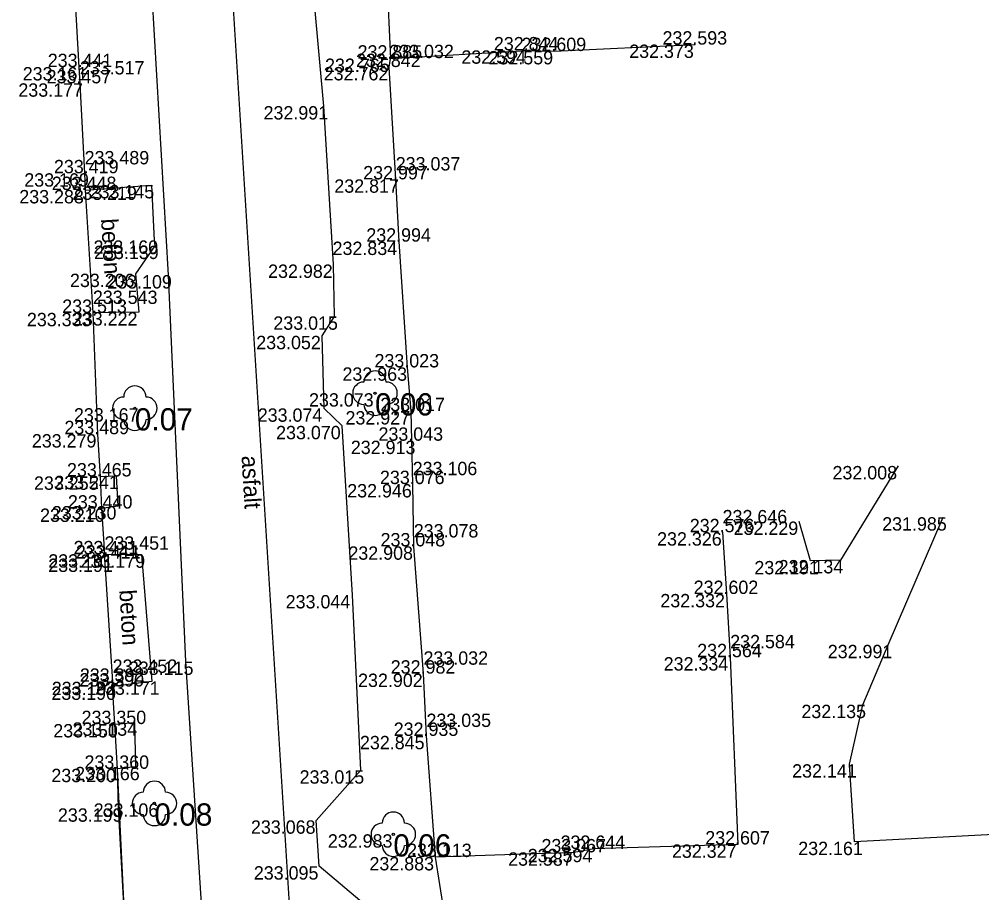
# Model space of a CAD drawing. Extents: x -599516 to -599132, y -1163668 to -1163119.
# Drawn here: x -599498.94 to -599477.33, y -1163341.49 to -1163321.87 of the extents above; entities that cross this region are included whole.
import ezdxf

# ---------------------------------------------------------------- set-up
doc = ezdxf.new("R2010")
doc.units = 0
for name, color, linetype in [('Bod-oznac1', 7, 'Continuous'), ('Bod-oznac2', 7, 'Continuous'), ('Bod-oznac3', 7, 'Continuous'), ('Bod-vyska1', 7, 'Continuous'), ('Bod-vyska2', 7, 'Continuous'), ('Bod-vyska3', 7, 'Continuous'), ('Z_cela-hrobu-dolni-linie', 7, 'Continuous'), ('Z_cela-hrobu-horni-linie', 7, 'Continuous'), ('Z_chodnik', 7, 'Continuous'), ('Z_kanalizace-destova', 7, 'Continuous'), ('Z_komunikace', 7, 'Continuous'), ('Z_nove-stromy-prumer-kmene', 7, 'Continuous'), ('Z_popis-budov-povrchu', 7, 'Continuous'), ('Z_stromy-nove-vysazene', 7, 'Continuous'), ('Z_zpevnene-plochy', 7, 'Continuous')]:
    doc.layers.add(name, color=color, linetype=linetype)

msp = doc.modelspace()

# ---------------------------------------------------------------- linework, layer by layer
at = {"layer": 'Bod-oznac1'}
for p, q in [((-599487.531, -1163322.57), (-599487.531, -1163322.57)), ((-599486.933, -1163322.585), (-599486.933, -1163322.585)), ((-599483.761, -1163322.44), (-599483.761, -1163322.44)), ((-599490.602, -1163322.755), (-599490.602, -1163322.755)), ((-599497.6, -1163322.946), (-599497.6, -1163322.946)), ((-599490.632, -1163322.944), (-599490.632, -1163322.944)), ((-599497.579, -1163323.311), (-599497.579, -1163323.311)), ((-599492.1, -1163323.823), (-599492.1, -1163323.823)), ((-599497.472, -1163325.331), (-599497.472, -1163325.331)), ((-599496.383, -1163325.629), (-599496.383, -1163325.629)), ((-599495.971, -1163325.595), (-599495.971, -1163325.595)), ((-599490.487, -1163325.468), (-599490.487, -1163325.468)), ((-599497.457, -1163325.707), (-599497.457, -1163325.707)), ((-599495.909, -1163326.84), (-599495.909, -1163326.84)), ((-599495.894, -1163326.958), (-599495.894, -1163326.958)), ((-599490.412, -1163326.867), (-599490.412, -1163326.867)), ((-599491.882, -1163327.381), (-599491.882, -1163327.381)), ((-599496.333, -1163327.587), (-599496.333, -1163327.587)), ((-599495.6, -1163327.62), (-599495.6, -1163327.62)), ((-599497.286, -1163328.467), (-599497.286, -1163328.467)), ((-599496.254, -1163328.452), (-599496.254, -1163328.452)), ((-599491.859, -1163328.546), (-599491.859, -1163328.546)), ((-599492.139, -1163328.983), (-599492.139, -1163328.983)), ((-599490.224, -1163329.692), (-599490.224, -1163329.692)), ((-599490.952, -1163330.272), (-599490.952, -1163330.272)), ((-599496.344, -1163330.609), (-599496.344, -1163330.609)), ((-599492.092, -1163330.613), (-599492.092, -1163330.613)), ((-599490.143, -1163330.675), (-599490.143, -1163330.675)), ((-599491.693, -1163331.006), (-599491.693, -1163331.006)), ((-599497.185, -1163331.192), (-599497.185, -1163331.192)), ((-599490.129, -1163331.339), (-599490.129, -1163331.339)), ((-599479.202, -1163331.907), (-599479.202, -1163331.907)), ((-599497.127, -1163332.142), (-599497.127, -1163332.142)), ((-599496.763, -1163332.126), (-599496.763, -1163332.126)), ((-599490.106, -1163332.313), (-599490.106, -1163332.313)), ((-599497.097, -1163332.863), (-599497.097, -1163332.863)), ((-599496.728, -1163332.807), (-599496.728, -1163332.807)), ((-599481.43, -1163333.154), (-599481.43, -1163333.154)), ((-599478.198, -1163333.058), (-599478.198, -1163333.058)), ((-599483.148, -1163333.395), (-599483.148, -1163333.395)), ((-599490.082, -1163333.713), (-599490.082, -1163333.713)), ((-599497.027, -1163333.987), (-599497.027, -1163333.987)), ((-599497.026, -1163333.89), (-599497.026, -1163333.89)), ((-599496.196, -1163333.894), (-599496.196, -1163333.894)), ((-599481.172, -1163334.041), (-599481.172, -1163334.041)), ((-599480.5, -1163334.019), (-599480.5, -1163334.019)), ((-599491.456, -1163334.806), (-599491.456, -1163334.806)), ((-599483.063, -1163334.782), (-599483.063, -1163334.782)), ((-599479.431, -1163335.925), (-599479.431, -1163335.925)), ((-599482.977, -1163336.202), (-599482.977, -1163336.202)), ((-599495.205, -1163336.299), (-599495.205, -1163336.299)), ((-599489.864, -1163336.571), (-599489.864, -1163336.571)), ((-599496.855, -1163336.861), (-599496.855, -1163336.861)), ((-599496.844, -1163336.754), (-599496.844, -1163336.754)), ((-599495.962, -1163336.747), (-599495.962, -1163336.747)), ((-599480, -1163337.271), (-599480, -1163337.271)), ((-599496.8, -1163337.704), (-599496.8, -1163337.704)), ((-599496.356, -1163337.667), (-599496.356, -1163337.667)), ((-599489.797, -1163337.97), (-599489.797, -1163337.97)), ((-599480.301, -1163338.607), (-599480.301, -1163338.607)), ((-599496.741, -1163338.709), (-599496.741, -1163338.709)), ((-599496.331, -1163338.666), (-599496.331, -1163338.666)), ((-599491.269, -1163338.743), (-599491.269, -1163338.743)), ((-599495.905, -1163339.486), (-599495.905, -1163339.486)), ((-599496.717, -1163339.598), (-599496.717, -1163339.598)), ((-599492.27, -1163339.868), (-599492.27, -1163339.868)), ((-599490.541, -1163340.18), (-599490.541, -1163340.18)), ((-599480.187, -1163340.348), (-599480.187, -1163340.348)), ((-599486.04, -1163340.508), (-599486.04, -1163340.508)), ((-599482.802, -1163340.409), (-599482.802, -1163340.409)), ((-599489.595, -1163340.691), (-599489.595, -1163340.691)), ((-599486.48, -1163340.586), (-599486.48, -1163340.586)), ((-599492.205, -1163340.898), (-599492.205, -1163340.898))]:
    msp.add_line(p, q, dxfattribs=at)
at = {"layer": 'Bod-oznac2'}
for p, q in [((-599487.531, -1163322.57), (-599487.531, -1163322.57)), ((-599486.933, -1163322.585), (-599486.933, -1163322.585)), ((-599483.761, -1163322.44), (-599483.761, -1163322.44)), ((-599490.602, -1163322.755), (-599490.602, -1163322.755)), ((-599497.6, -1163322.946), (-599497.6, -1163322.946)), ((-599490.632, -1163322.944), (-599490.632, -1163322.944)), ((-599497.579, -1163323.311), (-599497.579, -1163323.311)), ((-599497.472, -1163325.331), (-599497.472, -1163325.331)), ((-599490.487, -1163325.468), (-599490.487, -1163325.468)), ((-599497.457, -1163325.707), (-599497.457, -1163325.707)), ((-599490.412, -1163326.867), (-599490.412, -1163326.867)), ((-599497.286, -1163328.467), (-599497.286, -1163328.467)), ((-599490.224, -1163329.692), (-599490.224, -1163329.692)), ((-599490.143, -1163330.675), (-599490.143, -1163330.675)), ((-599497.185, -1163331.192), (-599497.185, -1163331.192)), ((-599490.129, -1163331.339), (-599490.129, -1163331.339)), ((-599497.127, -1163332.142), (-599497.127, -1163332.142)), ((-599490.106, -1163332.313), (-599490.106, -1163332.313)), ((-599497.097, -1163332.863), (-599497.097, -1163332.863)), ((-599483.148, -1163333.395), (-599483.148, -1163333.395)), ((-599490.082, -1163333.713), (-599490.082, -1163333.713)), ((-599497.027, -1163333.987), (-599497.027, -1163333.987)), ((-599497.026, -1163333.89), (-599497.026, -1163333.89)), ((-599483.063, -1163334.782), (-599483.063, -1163334.782)), ((-599482.977, -1163336.202), (-599482.977, -1163336.202)), ((-599489.864, -1163336.571), (-599489.864, -1163336.571)), ((-599496.855, -1163336.861), (-599496.855, -1163336.861)), ((-599496.844, -1163336.754), (-599496.844, -1163336.754)), ((-599496.8, -1163337.704), (-599496.8, -1163337.704)), ((-599489.797, -1163337.97), (-599489.797, -1163337.97)), ((-599496.741, -1163338.709), (-599496.741, -1163338.709)), ((-599486.04, -1163340.508), (-599486.04, -1163340.508)), ((-599482.802, -1163340.409), (-599482.802, -1163340.409)), ((-599489.595, -1163340.691), (-599489.595, -1163340.691)), ((-599486.48, -1163340.586), (-599486.48, -1163340.586))]:
    msp.add_line(p, q, dxfattribs=at)
at = {"layer": 'Bod-oznac3'}
for p, q in [((-599490.632, -1163322.944), (-599490.632, -1163322.944)), ((-599497.579, -1163323.311), (-599497.579, -1163323.311)), ((-599497.472, -1163325.331), (-599497.472, -1163325.331)), ((-599490.487, -1163325.468), (-599490.487, -1163325.468)), ((-599497.286, -1163328.467), (-599497.286, -1163328.467)), ((-599490.106, -1163332.313), (-599490.106, -1163332.313)), ((-599483.148, -1163333.395), (-599483.148, -1163333.395)), ((-599490.082, -1163333.713), (-599490.082, -1163333.713)), ((-599497.027, -1163333.987), (-599497.027, -1163333.987)), ((-599482.977, -1163336.202), (-599482.977, -1163336.202)), ((-599489.864, -1163336.571), (-599489.864, -1163336.571)), ((-599496.844, -1163336.754), (-599496.844, -1163336.754)), ((-599489.797, -1163337.97), (-599489.797, -1163337.97))]:
    msp.add_line(p, q, dxfattribs=at)
at = {"layer": 'Z_cela-hrobu-dolni-linie'}
for points in [[(-599497.76, -1163320.15), (-599497.6, -1163322.946), (-599497.579, -1163323.311), (-599497.472, -1163325.331), (-599497.457, -1163325.707), (-599497.286, -1163328.467), (-599497.185, -1163331.192), (-599497.127, -1163332.142), (-599497.097, -1163332.863), (-599497.026, -1163333.89), (-599497.027, -1163333.987), (-599496.844, -1163336.754), (-599496.855, -1163336.861), (-599496.8, -1163337.704), (-599496.741, -1163338.709), (-599496.717, -1163339.598), (-599496.572, -1163342.3)], [(-599489.595, -1163340.691), (-599489.797, -1163337.97), (-599489.864, -1163336.571), (-599490.082, -1163333.713), (-599490.106, -1163332.313), (-599490.129, -1163331.339), (-599490.143, -1163330.675), (-599490.224, -1163329.692), (-599490.412, -1163326.867), (-599490.487, -1163325.468), (-599490.632, -1163322.944), (-599490.602, -1163322.755)]]:
    msp.add_lwpolyline(points, dxfattribs=at)
at = {"layer": 'Z_cela-hrobu-horni-linie'}
msp.add_line((-599486.933, -1163322.585), (-599483.761, -1163322.44), dxfattribs=at)
for points in [[(-599497.76, -1163320.15), (-599497.6, -1163322.946), (-599497.579, -1163323.311), (-599497.579, -1163323.311), (-599497.472, -1163325.331), (-599497.472, -1163325.331), (-599497.457, -1163325.707), (-599497.286, -1163328.467), (-599497.286, -1163328.467), (-599497.185, -1163331.192), (-599497.127, -1163332.142), (-599497.097, -1163332.863), (-599497.026, -1163333.89), (-599497.027, -1163333.987), (-599497.027, -1163333.987), (-599496.844, -1163336.754), (-599496.844, -1163336.754), (-599496.855, -1163336.861), (-599496.8, -1163337.704), (-599496.741, -1163338.709), (-599496.572, -1163342.3)], [(-599490.143, -1163330.675), (-599490.224, -1163329.692), (-599490.412, -1163326.867), (-599490.487, -1163325.468), (-599490.487, -1163325.468), (-599490.632, -1163322.944), (-599490.632, -1163322.944), (-599490.602, -1163322.755), (-599487.531, -1163322.57)], [(-599486.48, -1163340.586), (-599489.595, -1163340.691), (-599489.797, -1163337.97), (-599489.797, -1163337.97), (-599489.864, -1163336.571), (-599489.864, -1163336.571), (-599490.082, -1163333.713), (-599490.082, -1163333.713), (-599490.106, -1163332.313), (-599490.106, -1163332.313), (-599490.129, -1163331.339)], [(-599483.148, -1163333.395), (-599483.148, -1163333.395), (-599483.063, -1163334.782), (-599482.977, -1163336.202), (-599482.977, -1163336.202), (-599482.802, -1163340.409), (-599486.04, -1163340.508)]]:
    msp.add_lwpolyline(points, dxfattribs=at)
at = {"layer": 'Z_chodnik'}
for points in [[(-599484.216, -1163313.364), (-599483.995, -1163316.575), (-599483.973, -1163317.652), (-599483.776, -1163320.433), (-599486.518, -1163320.62), (-599487.952, -1163320.689), (-599488.898, -1163320.771), (-599489.657, -1163320.871), (-599490.686, -1163320.962), (-599490.602, -1163322.755)], [(-599490.602, -1163322.755), (-599487.531, -1163322.57), (-599486.933, -1163322.585), (-599483.761, -1163322.44)], [(-599479.202, -1163331.907), (-599480.5, -1163334.019), (-599481.172, -1163334.041), (-599481.43, -1163333.154)], [(-599480.187, -1163340.348), (-599480.301, -1163338.607), (-599480, -1163337.271), (-599479.431, -1163335.925), (-599478.198, -1163333.058)], [(-599483.148, -1163333.395), (-599483.063, -1163334.782), (-599482.977, -1163336.202), (-599482.802, -1163340.409)]]:
    msp.add_lwpolyline(points, dxfattribs=at)
at = {"layer": 'Z_kanalizace-destova'}
msp.add_line((-599494.722, -1163312.287), (-599490.985, -1163372.054), dxfattribs=at)
at = {"layer": 'Z_komunikace'}
for points in [[(-599496.77, -1163314.404), (-599496.737, -1163314.993), (-599496.318, -1163316.655), (-599496.238, -1163317.885), (-599496.069, -1163319.529), (-599495.6, -1163327.62), (-599495.205, -1163336.299), (-599494.781, -1163342.887), (-599494.621, -1163344.702), (-599494.743, -1163347.039), (-599494.685, -1163348.117), (-599494.233, -1163354.684), (-599494.198, -1163357.286), (-599494.104, -1163358.744), (-599493.936, -1163362.675), (-599493.518, -1163365.083)], [(-599489.902, -1163364.909), (-599489.996, -1163362.923), (-599490.185, -1163358.938), (-599490.794, -1163358.344), (-599490.875, -1163356.055), (-599490.396, -1163355.473), (-599490.586, -1163351.474), (-599490.883, -1163347.19), (-599491.117, -1163346.799), (-599491.182, -1163345.761), (-599490.938, -1163344.776), (-599491.152, -1163341.79), (-599492.205, -1163340.898), (-599492.27, -1163339.868), (-599491.269, -1163338.743), (-599491.456, -1163334.806), (-599491.693, -1163331.006), (-599492.092, -1163330.613), (-599492.139, -1163328.983), (-599491.859, -1163328.546), (-599491.882, -1163327.381), (-599492.1, -1163323.823), (-599492.5, -1163319.448)], [(-599462.819, -1163331.018), (-599465.244, -1163331.841), (-599467.102, -1163332.921), (-599468.555, -1163334.295), (-599469.802, -1163335.87), (-599470.52, -1163337.655), (-599471.012, -1163339.618), (-599471.065, -1163339.885), (-599471.43, -1163340.076), (-599475.632, -1163340.11), (-599480.187, -1163340.348)], [(-599482.802, -1163340.409), (-599486.04, -1163340.508), (-599486.48, -1163340.586), (-599489.595, -1163340.691)], [(-599489.362, -1163345.833), (-599489.4, -1163341.92), (-599489.595, -1163340.691)]]:
    msp.add_lwpolyline(points, dxfattribs=at)
at = {"layer": 'Z_stromy-nove-vysazene'}
for centre in [(-599490.952, -1163330.272), (-599496.344, -1163330.609), (-599495.905, -1163339.486), (-599490.541, -1163340.18)]:
    msp.add_circle(centre, 0.025, dxfattribs=at)
for centre, start, end in [((-599490.952, -1163330.022), 0, 180), ((-599496.344, -1163330.359), 0, 180), ((-599491.202, -1163330.272), 90, 270), ((-599490.702, -1163330.272), 270, 90), ((-599496.594, -1163330.609), 90, 270), ((-599496.094, -1163330.609), 270, 90), ((-599490.952, -1163330.522), 180, 0), ((-599496.344, -1163330.859), 180, 0), ((-599495.905, -1163339.236), 0, 180), ((-599496.155, -1163339.486), 90, 270), ((-599495.655, -1163339.486), 270, 90), ((-599490.541, -1163339.93), 0, 180), ((-599495.905, -1163339.736), 180, 0), ((-599490.791, -1163340.18), 90, 270), ((-599490.291, -1163340.18), 270, 90), ((-599490.541, -1163340.43), 180, 0)]:
    msp.add_arc(centre, 0.25, start, end, dxfattribs=at)
at = {"layer": 'Z_zpevnene-plochy'}
for points in [[(-599497.457, -1163325.707), (-599496.383, -1163325.629), (-599495.971, -1163325.595), (-599495.909, -1163326.84), (-599495.894, -1163326.958), (-599496.333, -1163327.587), (-599496.254, -1163328.452), (-599497.286, -1163328.467)], [(-599497.127, -1163332.142), (-599496.763, -1163332.126), (-599496.728, -1163332.807), (-599497.097, -1163332.863)], [(-599497.026, -1163333.89), (-599496.196, -1163333.894), (-599495.962, -1163336.747), (-599496.855, -1163336.861)], [(-599496.8, -1163337.704), (-599496.356, -1163337.667), (-599496.331, -1163338.666), (-599496.741, -1163338.709)]]:
    msp.add_lwpolyline(points, dxfattribs=at)

# ---------------------------------------------------------------- texts
at = {"layer": 'Bod-vyska1'}
for s, p in [('232.594', (-599489.013, -1163322.87)), ('232.559', (-599488.403, -1163322.885)), ('232.373', (-599485.244, -1163322.74)), ('232.765', (-599492.074, -1163323.055)), ('233.161', (-599498.862, -1163323.246)), ('232.762', (-599492.104, -1163323.244)), ('233.177', (-599498.96, -1163323.611)), ('232.991', (-599493.455, -1163324.123)), ('233.169', (-599498.827, -1163325.631)), ('233.219', (-599497.749, -1163325.929)), ('233.145', (-599497.36, -1163325.895)), ('232.817', (-599491.866, -1163325.768)), ('233.288', (-599498.939, -1163326.007)), ('233.160', (-599497.273, -1163327.14)), ('233.139', (-599497.26, -1163327.258)), ('232.834', (-599491.905, -1163327.167)), ('232.982', (-599493.352, -1163327.681)), ('233.206', (-599497.801, -1163327.887)), ('233.109', (-599496.964, -1163327.92)), ('233.333', (-599498.768, -1163328.767)), ('233.222', (-599497.736, -1163328.752)), ('233.015', (-599493.235, -1163328.846)), ('233.052', (-599493.619, -1163329.283)), ('232.963', (-599491.683, -1163329.992)), ('233.073', (-599492.433, -1163330.572)), ('233.167', (-599497.712, -1163330.909)), ('233.074', (-599493.585, -1163330.913)), ('232.927', (-599491.615, -1163330.975)), ('233.070', (-599493.173, -1163331.306)), ('233.279', (-599498.657, -1163331.492)), ('232.913', (-599491.495, -1163331.639)), ('232.008', (-599480.68, -1163332.207)), ('233.255', (-599498.609, -1163332.442)), ('233.241', (-599498.152, -1163332.426)), ('232.946', (-599491.576, -1163332.613)), ('233.210', (-599498.473, -1163333.163)), ('233.230', (-599498.208, -1163333.107)), ('232.229', (-599482.9, -1163333.454)), ('231.985', (-599479.564, -1163333.358)), ('232.326', (-599484.618, -1163333.695)), ('232.908', (-599491.55, -1163334.013)), ('233.191', (-599498.289, -1163334.287)), ('233.191', (-599498.288, -1163334.19)), ('233.179', (-599497.564, -1163334.194)), ('232.191', (-599482.434, -1163334.341)), ('232.134', (-599481.889, -1163334.319)), ('233.044', (-599492.958, -1163335.106)), ('232.332', (-599484.545, -1163335.082)), ('232.991', (-599480.786, -1163336.225)), ('232.334', (-599484.47, -1163336.502)), ('233.115', (-599496.479, -1163336.599)), ('232.902', (-599491.332, -1163336.871)), ('233.190', (-599498.219, -1163337.161)), ('233.192', (-599498.21, -1163337.054)), ('233.171', (-599497.237, -1163337.047)), ('232.135', (-599481.378, -1163337.571)), ('233.150', (-599498.176, -1163338.004)), ('233.134', (-599497.745, -1163337.967)), ('232.845', (-599491.29, -1163338.27)), ('232.141', (-599481.586, -1163338.907)), ('233.200', (-599498.219, -1163339.009)), ('233.166', (-599497.686, -1163338.966)), ('233.015', (-599492.645, -1163339.043)), ('233.106', (-599497.269, -1163339.786)), ('233.199', (-599498.072, -1163339.898)), ('233.068', (-599493.738, -1163340.168)), ('232.983', (-599492.011, -1163340.48)), ('232.161', (-599481.449, -1163340.648)), ('232.587', (-599487.963, -1163340.886)), ('232.594', (-599487.522, -1163340.808)), ('232.327', (-599484.285, -1163340.709)), ('232.883', (-599491.077, -1163340.991)), ('233.095', (-599493.673, -1163341.198))]:
    msp.add_text(s, height=0.3, dxfattribs=at).set_placement(p)
at = {"layer": 'Bod-vyska2'}
for s, p in [('232.593', (-599484.496, -1163322.44)), ('232.844', (-599488.283, -1163322.57)), ('232.609', (-599487.661, -1163322.585)), ('233.441', (-599498.3, -1163322.946)), ('232.842', (-599491.378, -1163322.944)), ('232.885', (-599491.343, -1163322.755)), ('233.457', (-599498.326, -1163323.311)), ('233.419', (-599498.161, -1163325.331)), ('232.997', (-599491.217, -1163325.468)), ('233.448', (-599498.209, -1163325.707)), ('232.994', (-599491.147, -1163326.867)), ('233.513', (-599497.975, -1163328.467)), ('233.023', (-599490.964, -1163329.692)), ('233.017', (-599490.832, -1163330.675)), ('233.489', (-599497.926, -1163331.192)), ('233.043', (-599490.874, -1163331.339)), ('233.465', (-599497.868, -1163332.142)), ('233.076', (-599490.841, -1163332.313)), ('233.440', (-599497.848, -1163332.863)), ('232.576', (-599483.884, -1163333.395)), ('233.048', (-599490.827, -1163333.713)), ('233.421', (-599497.72, -1163333.89)), ('233.411', (-599497.669, -1163333.987)), ('232.602', (-599483.797, -1163334.782)), ('232.564', (-599483.718, -1163336.202)), ('233.392', (-599497.579, -1163336.754)), ('232.982', (-599490.599, -1163336.571)), ('233.390', (-599497.589, -1163336.861)), ('233.350', (-599497.54, -1163337.704)), ('232.935', (-599490.532, -1163337.97)), ('233.360', (-599497.475, -1163338.709)), ('232.607', (-599483.537, -1163340.409)), ('233.067', (-599487.215, -1163340.586)), ('232.644', (-599486.786, -1163340.508)), ('233.113', (-599490.232, -1163340.691))]:
    msp.add_text(s, height=0.3, dxfattribs=at).set_placement(p)
at = {"layer": 'Bod-vyska3'}
for s, p in [('233.032', (-599490.632, -1163322.744)), ('233.517', (-599497.579, -1163323.111)), ('233.489', (-599497.472, -1163325.131)), ('233.037', (-599490.487, -1163325.268)), ('233.543', (-599497.286, -1163328.267)), ('233.106', (-599490.106, -1163332.113)), ('232.646', (-599483.148, -1163333.195)), ('233.078', (-599490.082, -1163333.513)), ('233.451', (-599497.027, -1163333.787)), ('232.584', (-599482.977, -1163336.002)), ('233.452', (-599496.844, -1163336.554)), ('233.032', (-599489.864, -1163336.371)), ('233.035', (-599489.797, -1163337.77))]:
    msp.add_text(s, height=0.3, dxfattribs=at).set_placement(p)
at = {"layer": 'Z_nove-stromy-prumer-kmene'}
for s, p in [('0.06', (-599490.952, -1163330.772)), ('0.07', (-599496.344, -1163331.109)), ('0.08', (-599495.905, -1163339.986)), ('0.06', (-599490.541, -1163340.68))]:
    msp.add_text(s, height=0.5, dxfattribs=at).set_placement(p)
at = {"layer": 'Z_popis-budov-povrchu'}
for s, p in [('beton', (-599497.105, -1163326.358)), ('asfalt', (-599493.95, -1163331.683)), ('beton', (-599496.694, -1163334.696))]:
    msp.add_text(s, height=0.375, rotation=273.4503, dxfattribs=at).set_placement(p)

doc.saveas('drawing.dxf')
